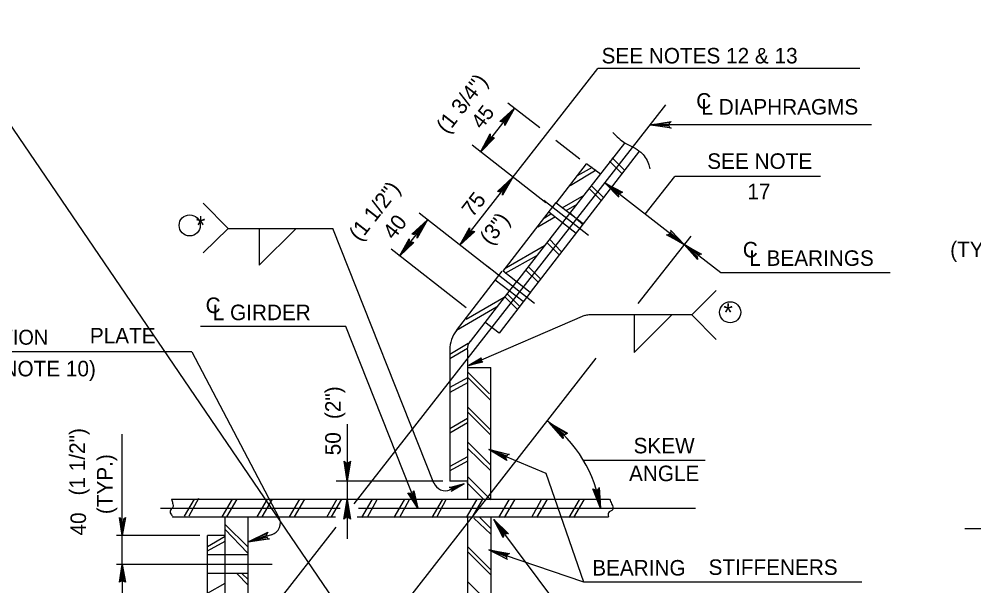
# Model space of a CAD drawing. Extents: x 634656 to 641360, y 298715 to 301183.
# Drawn here: x 640490.1 to 640674.7, y 299553.5 to 299663.1 of the extents above; entities that cross this region are included whole.
import ezdxf

# ---------------------------------------------------------------- set-up
doc = ezdxf.new("R2010")
doc.units = 0
for name, color, linetype in [('1', 7, 'Continuous'), ('2', 7, 'Continuous'), ('40', 7, 'Continuous')]:
    doc.layers.add(name, color=color, linetype=linetype)

msp = doc.modelspace()

# ---------------------------------------------------------------- linework, layer by layer
at = {"layer": '1'}
msp.add_line((640203.02, 300061.47), (641094.36, 298753.08), dxfattribs=at)
for points in [[(640554.02, 299577.46), (640553.75, 299577.32), (640553.55, 299573.77), (640554.02, 299577.46), (640554.18, 299577.65), (640553.55, 299573.77), (640553.38, 299577.32), (640553.11, 299577.45), (640553.55, 299573.77), (640552.94, 299577.65), (640553.11, 299577.45)], [(640553.09, 299566.58), (640553.36, 299566.71), (640553.55, 299570.27), (640553.09, 299566.58), (640552.93, 299566.39), (640553.55, 299570.27), (640553.73, 299566.72), (640553.99, 299566.59), (640553.55, 299570.27), (640554.17, 299566.39), (640553.99, 299566.59)], [(640583.75, 299563.11), (640583.88, 299563.38), (640581.9, 299566.34), (640583.75, 299563.11), (640583.73, 299562.86), (640581.9, 299566.34), (640584.18, 299563.61), (640584.46, 299563.66), (640581.9, 299566.34), (640584.73, 299563.61), (640584.46, 299563.66)]]:
    msp.add_lwpolyline(points, dxfattribs=at)
at = {"layer": '2'}
for p, q in [((640575.35, 299619.38), (640601.99, 299653.52)), ((640652.71, 299653.52), (640601.99, 299653.52)), ((640590.77, 299642.07), (640584.62, 299646.85)), ((640554.91, 299569.37), (640615.18, 299646.52)), ((640579.34, 299637.42), (640585.93, 299645.89)), ((640585.93, 299645.89), (640585.93, 299645.89)), ((640654.93, 299642.64), (640612.18, 299642.64)), ((640598.55, 299636.02), (640593.89, 299639.64)), ((640591.99, 299627.55), (640577.72, 299638.69)), ((640607.18, 299639.14), (640596.55, 299625.52)), ((640610.05, 299637.64), (640599.18, 299623.52)), ((640604.8, 299636.27), (640607.18, 299633.89)), ((640593.93, 299627.52), (640599.8, 299635.14)), ((640601.68, 299633.89), (640596.68, 299630.89)), ((640600.93, 299634.39), (640598.05, 299632.77)), ((640602.55, 299633.14), (640599.8, 299635.14)), ((640604.3, 299635.64), (640606.68, 299633.27)), ((640611.18, 299625.39), (640616.93, 299632.64)), ((640645.05, 299632.64), (640616.93, 299632.64)), ((640600.3, 299630.39), (640602.68, 299628.02)), ((640600.8, 299630.89), (640603.05, 299628.64)), ((640618.68, 299619.52), (640603.43, 299631.39)), ((640599.3, 299629.02), (640595.05, 299626.52)), ((640583.68, 299614.39), (640593.93, 299627.64)), ((640600.18, 299621.27), (640591.55, 299628.02)), ((640599.18, 299623.52), (640593.93, 299627.52)), ((640597.93, 299627.27), (640595.8, 299626.02)), ((640581.13, 299614.85), (640567.47, 299625.56)), ((640596.55, 299625.52), (640586.3, 299612.27)), ((640593.8, 299624.89), (640590.43, 299622.89)), ((640592.93, 299625.39), (640591.68, 299624.64)), ((640597.8, 299621.64), (640592.55, 299625.77)), ((640596.68, 299625.64), (640599.05, 299623.39)), ((640563.68, 299617.27), (640569.12, 299624.26)), ((640599.18, 299623.52), (640588.93, 299610.27)), ((640530.55, 299622.64), (640550.8, 299622.64)), ((640536.55, 299622.64), (640536.55, 299615.52)), ((640536.55, 299615.52), (640543.68, 299622.64)), ((640570.3, 299573.39), (640550.8, 299622.64)), ((640609.8, 299608.14), (640620.05, 299621.14)), ((640591.68, 299619.27), (640583.93, 299614.77)), ((640592.18, 299619.89), (640594.55, 299617.52)), ((640592.68, 299620.52), (640594.93, 299618.14)), ((640625.8, 299614.02), (640618.68, 299619.52)), ((640576.55, 299607.27), (640562.05, 299618.64)), ((640563.68, 299617.27), (640563.68, 299617.27)), ((640563.68, 299617.27), (640563.68, 299617.27)), ((640590.3, 299617.39), (640584.05, 299613.89)), ((640574.68, 299602.89), (640583.55, 299614.39)), ((640589.8, 299608.14), (640580.68, 299615.27)), ((640588.93, 299610.27), (640583.68, 299614.39)), ((640588.05, 299614.64), (640590.43, 299612.27)), ((640588.55, 299615.27), (640590.93, 299612.89)), ((640658.55, 299614.02), (640625.8, 299614.02)), ((640586.3, 299612.39), (640577.3, 299600.77)), ((640587.55, 299608.52), (640582.18, 299612.64)), ((640589.05, 299610.39), (640582.93, 299602.39)), ((640584.43, 299610.02), (640586.8, 299607.64)), ((640583.93, 299609.27), (640576.55, 299605.02)), ((640584.05, 299609.39), (640586.43, 299607.02)), ((640582.43, 299607.39), (640574.68, 299602.89)), ((640599.43, 299605.77), (640577.05, 299596.14)), ((640582.93, 299602.39), (640580.18, 299604.52)), ((640620.18, 299605.89), (640600.3, 299605.89)), ((640609.05, 299605.89), (640609.05, 299598.64)), ((640609.05, 299598.64), (640616.3, 299605.89)), ((640609.05, 299605.89), (640609.05, 299598.64)), ((640609.05, 299598.64), (640616.3, 299605.89)), ((640553.3, 299603.64), (640525.18, 299603.64)), ((640567.18, 299568.52), (640553.3, 299603.64)), ((640523.54, 299598.78), (640471.54, 299598.78)), ((640523.54, 299598.78), (640540.3, 299566.77)), ((640576.93, 299600.39), (640573.43, 299598.27)), ((640576.8, 299599.39), (640573.43, 299597.39)), ((640573.43, 299599.14), (640573.43, 299573.77)), ((640576.8, 299599.14), (640576.8, 299570.27)), ((640556.33, 299539.43), (640601.68, 299597.52)), ((640576.8, 299595.77), (640581.3, 299595.77)), ((640581.3, 299570.27), (640581.3, 299595.77)), ((640576.8, 299593.77), (640573.43, 299591.89)), ((640576.8, 299594.89), (640581.05, 299590.64)), ((640576.8, 299593.89), (640581.18, 299589.52)), ((640576.8, 299592.77), (640573.43, 299590.89)), ((640576.8, 299588.14), (640581.3, 299583.64)), ((640576.8, 299585.89), (640573.43, 299583.89)), ((640576.8, 299587.14), (640581.3, 299582.64)), ((640553.55, 299584.79), (640553.55, 299573.77)), ((640576.8, 299585.02), (640573.43, 299583.02)), ((640510.05, 299557.64), (640510.05, 299582.86)), ((640576.8, 299581.39), (640581.3, 299576.89)), ((640576.8, 299580.14), (640581.3, 299575.77)), ((640592.05, 299575.27), (640580.93, 299579.89)), ((640576.8, 299577.64), (640573.43, 299575.77)), ((640576.68, 299578.39), (640573.55, 299576.64)), ((640622.8, 299577.77), (640599.3, 299577.77)), ((640599.3, 299554.27), (640592.05, 299575.27)), ((640572.05, 299573.77), (640551.43, 299573.77)), ((640553.55, 299573.77), (640553.55, 299570.27)), ((640576.8, 299573.77), (640573.43, 299573.77)), ((640573.43, 299572.14), (640576.18, 299573.27)), ((640576.68, 299573.52), (640579.93, 299570.27)), ((640576.8, 299574.64), (640581.3, 299570.14)), ((640519.55, 299570.27), (640604.3, 299570.27)), ((640523.93, 299570.27), (640522.05, 299567.02)), ((640524.8, 299570.39), (640522.93, 299567.02)), ((640531.3, 299570.27), (640529.3, 299566.89)), ((640532.18, 299570.27), (640530.18, 299566.89)), ((640538.05, 299570.27), (640536.05, 299566.89)), ((640539.05, 299570.27), (640537.05, 299566.89)), ((640544.3, 299570.27), (640542.3, 299566.89)), ((640545.3, 299570.27), (640543.3, 299566.89)), ((640551.55, 299570.27), (640549.55, 299566.77)), ((640552.43, 299570.27), (640550.43, 299566.89)), ((640553.55, 299570.27), (640553.55, 299562.64)), ((640558.3, 299570.14), (640556.3, 299566.77)), ((640559.3, 299570.14), (640557.43, 299566.77)), ((640564.55, 299570.14), (640562.55, 299566.77)), ((640565.55, 299570.14), (640563.68, 299566.77)), ((640571.93, 299570.14), (640569.93, 299566.77)), ((640572.68, 299570.27), (640570.8, 299566.77)), ((640578.55, 299570.14), (640576.55, 299566.77)), ((640579.68, 299570.14), (640577.68, 299566.77)), ((640584.8, 299570.14), (640582.8, 299566.77)), ((640585.93, 299570.14), (640583.93, 299566.77)), ((640591.05, 299570.14), (640589.18, 299566.77)), ((640592.18, 299570.14), (640590.18, 299566.77)), ((640598.43, 299570.14), (640596.43, 299566.77)), ((640599.3, 299570.14), (640597.3, 299566.77)), ((640517.43, 299568.52), (640552.17, 299568.52)), ((640533.93, 299568.64), (640533.93, 299568.64)), ((640555.74, 299568.52), (640620.93, 299568.52)), ((640519.8, 299566.89), (640551.29, 299566.89)), ((640529.93, 299542.14), (640529.93, 299566.89)), ((640534.43, 299541.27), (640534.43, 299566.89)), ((640555.49, 299566.89), (640604.05, 299566.89)), ((640576.8, 299566.77), (640576.8, 299534.52)), ((640581.3, 299563.52), (640578.05, 299566.64)), ((640581.3, 299564.64), (640579.18, 299566.77)), ((640581.3, 299566.77), (640581.3, 299534.52)), ((640602.19, 299539.3), (640581.9, 299566.34)), ((640490.68, 299487.14), (640551.4, 299564.88)), ((640529.93, 299565.39), (640534.43, 299561.02)), ((640529.93, 299564.39), (640534.3, 299559.89)), ((640759.88, 299564.55), (640673, 299564.55)), ((640525.05, 299563.27), (640508.93, 299563.27)), ((640526.55, 299542.14), (640526.55, 299563.27)), ((640529.93, 299563.27), (640526.55, 299563.27)), ((640526.55, 299561.14), (640529.93, 299563.14)), ((640526.55, 299560.27), (640529.93, 299562.14)), ((640538.93, 299563.39), (640534.43, 299562.02)), ((640581.3, 299556.64), (640576.8, 299561.14)), ((640581.3, 299555.64), (640576.8, 299560.14)), ((640599.3, 299554.27), (640580.93, 299560.52)), ((640534.43, 299559.52), (640526.55, 299559.52)), ((640524.8, 299557.64), (640508.93, 299557.64)), ((640510.05, 299557.64), (640510.05, 299546.89)), ((640539.05, 299557.64), (640524.8, 299557.64)), ((640534.43, 299555.89), (640526.55, 299555.89)), ((640532.18, 299555.89), (640534.43, 299553.64)), ((640533.18, 299555.89), (640534.43, 299554.77)), ((640526.55, 299552.14), (640529.93, 299554.02)), ((640581.3, 299549.89), (640576.8, 299554.39)), ((640653.05, 299554.27), (640599.3, 299554.27))]:
    msp.add_line(p, q, dxfattribs=at)
for points in [[(640583.3, 299643.27), (640583.55, 299643.27), (640585.93, 299645.89), (640583.3, 299643.27), (640583.05, 299643.27), (640585.93, 299645.89), (640583.93, 299643.02), (640584.05, 299642.77), (640585.93, 299645.89), (640584.05, 299642.52), (640584.05, 299642.77)], [(640615.93, 299642.14), (640615.8, 299642.39), (640612.18, 299642.64), (640615.93, 299642.14), (640616.18, 299642.02), (640612.18, 299642.64), (640615.8, 299642.77), (640615.93, 299643.02), (640612.18, 299642.64), (640616.18, 299643.27), (640615.93, 299643.02)], [(640581.93, 299640.14), (640581.55, 299640.14), (640579.3, 299637.39), (640581.93, 299640.14), (640582.05, 299640.14), (640579.3, 299637.39), (640581.3, 299640.39), (640581.18, 299640.64), (640579.3, 299637.39), (640581.18, 299640.89), (640581.18, 299640.64)], [(640582.86, 299629.78), (640583.11, 299629.78), (640585.61, 299632.53), (640582.86, 299629.78), (640582.61, 299629.78), (640585.61, 299632.53), (640583.61, 299629.53), (640583.61, 299629.28), (640585.61, 299632.53), (640583.61, 299629.03), (640583.61, 299629.28)], [(640605.93, 299628.89), (640606.05, 299629.14), (640603.43, 299631.39), (640605.93, 299628.89), (640606.05, 299628.64), (640603.43, 299631.39), (640606.3, 299629.39), (640606.55, 299629.52), (640603.43, 299631.39), (640606.8, 299629.64), (640606.55, 299629.52)], [(640525.68, 299627.52), (640530.55, 299622.64), (640525.68, 299617.89)], [(640566.3, 299621.52), (640566.55, 299621.52), (640569.05, 299624.27), (640566.3, 299621.52), (640566.05, 299621.52), (640569.05, 299624.27), (640567.05, 299621.27), (640567.05, 299621.02), (640569.05, 299624.27), (640567.05, 299620.77), (640567.05, 299621.02)], [(640577.98, 299622), (640577.73, 299622), (640575.35, 299619.38), (640577.98, 299622), (640578.23, 299622), (640575.35, 299619.38), (640577.35, 299622.25), (640577.23, 299622.5), (640575.35, 299619.38), (640577.23, 299622.75), (640577.23, 299622.5)], [(640616.18, 299622.14), (640616.05, 299621.77), (640618.68, 299619.52), (640616.18, 299622.14), (640616.05, 299622.27), (640618.68, 299619.52), (640615.8, 299621.52), (640615.55, 299621.39), (640618.68, 299619.52), (640615.3, 299621.39), (640615.55, 299621.39)], [(640566.3, 299619.89), (640565.93, 299619.89), (640563.68, 299617.27), (640566.3, 299619.89), (640566.43, 299619.89), (640563.68, 299617.27), (640565.68, 299620.14), (640565.55, 299620.39), (640563.68, 299617.27), (640565.55, 299620.64), (640565.55, 299620.39)], [(640621.3, 299616.89), (640621.3, 299617.14), (640618.68, 299619.52), (640621.3, 299616.89), (640621.3, 299616.64), (640618.68, 299619.52), (640621.55, 299617.52), (640621.8, 299617.64), (640618.68, 299619.52), (640622.05, 299617.64), (640621.8, 299617.64)], [(640624.93, 299610.64), (640620.18, 299605.89), (640624.93, 299601.14)], [(640579.68, 299596.89), (640579.55, 299597.02), (640577.05, 299596.14), (640579.68, 299596.89), (640579.8, 299596.77), (640577.05, 299596.14), (640579.43, 299597.27), (640579.43, 299597.52), (640577.05, 299596.14), (640579.55, 299597.64), (640579.43, 299597.52)], [(640595.3, 299582.27), (640595.3, 299582.52), (640592.68, 299585.02), (640595.3, 299582.27), (640595.3, 299582.02), (640592.68, 299585.02), (640595.55, 299582.77), (640595.93, 299582.89), (640592.68, 299585.02), (640596.18, 299583.02), (640595.93, 299582.89)], [(640584.3, 299578.02), (640584.3, 299578.27), (640580.93, 299579.89), (640584.3, 299578.02), (640584.43, 299577.77), (640580.93, 299579.89), (640584.43, 299578.64), (640584.68, 299578.89), (640580.93, 299579.89), (640584.93, 299578.89), (640584.68, 299578.89)], [(640573.55, 299572.52), (640573.68, 299572.39), (640576.18, 299573.27), (640573.55, 299572.52), (640573.3, 299572.52), (640576.18, 299573.27), (640573.8, 299572.14), (640573.8, 299571.89), (640576.18, 299573.27), (640573.68, 299571.77), (640573.8, 299571.89)], [(640566.3, 299571.77), (640566.18, 299571.52), (640567.18, 299568.52), (640566.3, 299571.77), (640566.43, 299571.89), (640567.18, 299568.52), (640565.8, 299571.39), (640565.55, 299571.39), (640567.18, 299568.52), (640565.3, 299571.52), (640565.55, 299571.39)], [(640602.18, 299572.27), (640601.93, 299572.14), (640602.55, 299568.52), (640602.18, 299572.27), (640602.3, 299572.52), (640602.55, 299568.52), (640601.55, 299572.02), (640601.3, 299572.14), (640602.55, 299568.52), (640601.05, 299572.27), (640601.3, 299572.14)], [(640510.43, 299566.52), (640510.3, 299566.39), (640510.05, 299563.27), (640510.43, 299566.52), (640510.68, 299566.77), (640510.05, 299563.27), (640509.93, 299566.39), (640509.68, 299566.52), (640510.05, 299563.27), (640509.55, 299566.77), (640509.68, 299566.52)], [(640538.3, 299562.64), (640538.05, 299562.89), (640534.43, 299562.02), (640538.3, 299562.64), (640538.55, 299562.64), (640534.43, 299562.02), (640537.93, 299563.27), (640538.05, 299563.64), (640534.43, 299562.02), (640538.18, 299563.89), (640538.05, 299563.64)], [(640584.43, 299558.77), (640584.43, 299559.14), (640580.93, 299560.52), (640584.43, 299558.77), (640584.55, 299558.64), (640580.93, 299560.52), (640584.55, 299559.52), (640584.68, 299559.64), (640580.93, 299560.52), (640584.93, 299559.77), (640584.68, 299559.64)], [(640509.68, 299554.39), (640509.93, 299554.52), (640510.05, 299557.64), (640509.68, 299554.39), (640509.55, 299554.27), (640510.05, 299557.64), (640510.18, 299554.52), (640510.43, 299554.39), (640510.05, 299557.64), (640510.68, 299554.27), (640510.43, 299554.39)]]:
    msp.add_lwpolyline(points, dxfattribs=at)
for centre in [(640523.1, 299623.21), (640627.6, 299606.42)]:
    msp.add_circle(centre, 2.04, dxfattribs=at)
for centre, radius, start, end in [((640600.34, 299603.5), 2.4, 90, 113.237), ((640579.39, 299599.19), 6, 142.0747, 180), ((640579.39, 299599.19), 2.63, 142.0747, 180), ((640577.77, 299564.98), 25.01, 8.0693, 54.5334), ((640572.55, 299574.32), 2.4, 201.5588, 293.0255), ((640538.23, 299565.71), 2.4, 286.8008, 27.646)]:
    msp.add_arc(centre, radius, start, end, dxfattribs=at)
for points in [[(640604.93, 299641.14), (640607.3, 299639.14), (640610.3, 299637.39), (640611.8, 299635.14), (640612.05, 299634.14)], [(640519.55, 299570.27), (640519.8, 299569.52), (640519.8, 299568.64), (640519.3, 299568.02), (640519.55, 299567.27), (640519.93, 299566.77)], [(640604.3, 299570.27), (640604.68, 299569.39), (640604.93, 299568.27), (640604.05, 299567.64), (640604.05, 299566.89)]]:
    msp.add_spline(points, degree=3, dxfattribs=at)

# ---------------------------------------------------------------- texts
for s, height, p in [('SEE NOTES 12 & 13', 3, (640602.74, 299654.52)), ('C', 3, (640621.05, 299645.77)), ('L DIAPHRAGMS', 3, (640622.05, 299644.64)), ('SEE NOTE', 3, (640623.18, 299634.14)), ('17', 3, (640630.93, 299628.27)), ('*', 3.5, (640524.3, 299621.52)), ('C', 3, (640630.05, 299617.02)), ('(TYP.)', 3, (640670.15, 299617.07)), ('L BEARINGS', 3, (640631.3, 299615.39)), ('C', 3, (640526.18, 299606.27)), ('*', 3.5, (640626.3, 299604.64)), ('L GIRDER', 3, (640527.55, 299604.89)), (' CONNECTION', 2.8792, (640468.79, 299600.15)), ('PLATE', 3, (640503.79, 299600.4)), ('(SEE NOTE 10)', 3, (640476.42, 299594.03)), ('SKEW', 3, (640608.93, 299579.14)), ('ANGLE', 3, (640608.05, 299573.77)), ('BEARING', 3, (640600.93, 299555.52)), ('STIFFENERS', 3, (640623.43, 299555.64))]:
    msp.add_text(s, height=height, dxfattribs=at).set_placement(p)
for s, height, rotation, p in [('45', 2.875, 52.1059, (640579.55, 299641.64)), ('75', 3, 52.1059, (640577.81, 299624.63)), ('40', 3, 52.1059, (640562.55, 299620.27)), ('50', 3, 90, (640552.3, 299578.77)), ('(TYP.)', 3, 90, (640508.17, 299567.39)), ('40', 3, 90, (640503.04, 299563.26))]:
    msp.add_text(s, height=height, rotation=rotation, dxfattribs=at).set_placement(p)
at = {"layer": '40'}
for s, rotation, p in [('(1 3/4")', 51.9975, (640572.89, 299640.75)), ('(1 1/2")', 51.9975, (640555.99, 299619.96)), ('(3")', 51.9975, (640581.28, 299619.21)), ('(2")', 90, (640552.3, 299585.77)), ('(1 1/2")', 90, (640502.84, 299571))]:
    msp.add_text(s, height=3, rotation=rotation, dxfattribs=at).set_placement(p)

doc.saveas('drawing.dxf')
